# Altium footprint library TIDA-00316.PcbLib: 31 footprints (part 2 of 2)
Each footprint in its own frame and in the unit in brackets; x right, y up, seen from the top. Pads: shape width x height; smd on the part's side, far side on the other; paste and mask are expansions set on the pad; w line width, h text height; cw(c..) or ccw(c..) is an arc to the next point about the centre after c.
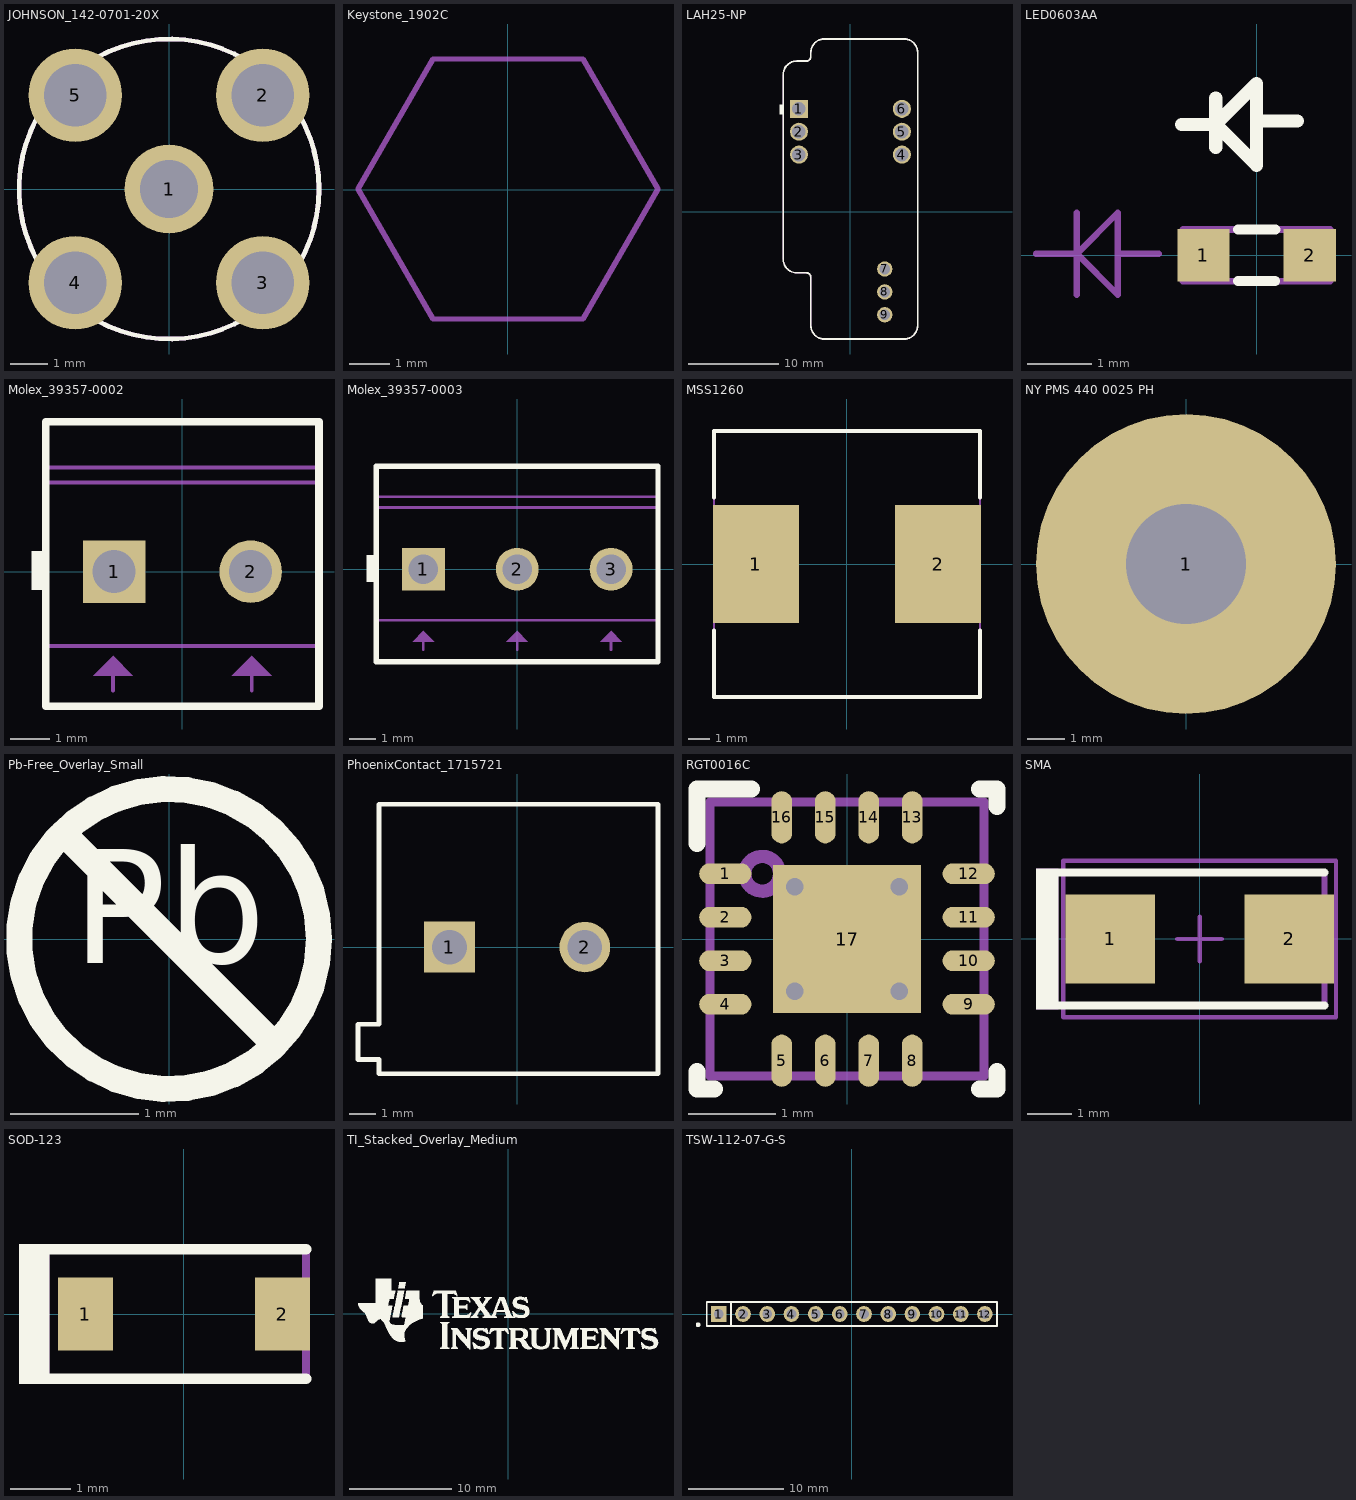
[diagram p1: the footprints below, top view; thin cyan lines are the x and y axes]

## JOHNSON_142-0701-20X [mil] "Johnson Components recommended land pattern"
height 375
pads (5):
  round 95 hole 62: 1(0,0)
  round 100 hole 67: 2(100,100) 3(100,-100) 4(-100,-100) 5(-100,100)
Top Overlay:
  circle w5: c0,0 r160
Mechanical 5:
  circle w5: c0,0 r160
  text ".Designator" at -121,-18 h30
3D body: height 375, standoff -155, extent -155.99,-155.8 156.01,155.8

## Keystone_1902C [mil] "Hex Standoff, 4-40 threaded, nylon"
height 500
pads (1):
  round 1 on Mech3: 0(0,0)
Mechanical 5:
  lines w5: -145.29,0.49 -72.56,-125.49 72.92,-125.49 145.65,0.49 72.92,126.47 -72.56,126.47 -145.29,0.49
  text ".Designator" at -60,-20 h30
3D body: height 501, standoff 1, extent -144.95,-125.98 146,125.98

## LAH25-NP [mm] "TH, 9-Leads, Body 14.93x33.3mm"
height 21.2
pads (9):
  rect 2x2 hole 1.5: 1(-5.715,11.43)
  round 2 hole 1.5: 2(-5.715,8.89) 3(-5.715,6.35) 4(5.715,6.35) 5(5.715,8.89) 6(5.715,11.43)
  round 1.7 hole 1.2: 7(3.81,-6.35) 8(3.81,-8.89) 9(3.81,-11.43)
Top Overlay:
  region: -7.9,11.9 -7.9,10.8 -7.465,10.8 -7.465,11.9
  lines w0.2: -4.402,-7.114 -4.402,-7.122 -4.401,-7.13 -4.401,-7.138 -4.4,-7.146 -4.4,-7.153 -4.4,-7.161 ; -7.465,-5.27 ccw(c-5.965,-5.27) -5.965,-6.77 -4.9,-6.77 cw(c-4.9,-7.27) -4.4,-7.27 -4.4,-12.62 ccw(c-2.9,-12.62) -2.9,-14.12 5.965,-14.12 ccw(c5.965,-12.62) 7.465,-12.62 7.465,17.68 ccw(c5.965,17.68) 5.965,19.18 -2.9,19.18 ccw(c-2.9,17.68) -4.4,17.68 -4.4,17.23 cw(c-4.9,17.23) -4.9,16.73 -5.965,16.73 ccw(c-5.965,15.23) -7.465,15.23 -7.465,-5.27
Mechanical 5:
  lines w0.1: -4.402,-7.114 -4.402,-7.122 -4.401,-7.13 -4.401,-7.138 -4.4,-7.146 -4.4,-7.153 -4.4,-7.161 ; -7.465,-5.27 ccw(c-5.965,-5.27) -5.965,-6.77 -4.9,-6.77 cw(c-4.9,-7.27) -4.4,-7.27 -4.4,-12.62 ccw(c-2.9,-12.62) -2.9,-14.12 5.965,-14.12 ccw(c5.965,-12.62) 7.465,-12.62 7.465,17.68 ccw(c5.965,17.68) 5.965,19.18 -2.9,19.18 ccw(c-2.9,17.68) -4.4,17.68 -4.4,17.23 cw(c-4.9,17.23) -4.9,16.73 -5.965,16.73 ccw(c-5.965,15.23) -7.465,15.23 -7.465,-5.27
  text ".Designator" at 0.432,3.581 h0.76
3D body: height 21.15, standoff -3.55, extent -7.439,-14.12 7.5,19.18

## LED0603AA [mil]
pads (2):
  rect 32x32 smd: 1(-32.48,0) 2(32.48,0)
Top Overlay:
  lines w6: -11.42,-15.75 11.42,-15.75 ; -11.42,15.75 11.42,15.75
  lines w8: -46,80 -25,80 ; -25,66 -25,96 ; 0,82 25,82 ; -25,80 0,55 0,105 -25,80
Mechanical 5:
  lines w4: -45,-15.75 45,-15.75 45,15.75 -45,15.75 -45,-15.75
  text ".Designator" at 31,62 h30
Mechanical 15:
  lines w1: -31.5,-15.75 -31.5,15.75 31.5,15.75 31.5,-15.75 -31.5,-15.75
  lines w3.94: -134.79,0.96 -109.79,0.96 ; -109.79,-24.04 -109.79,25.96 ; -84.79,0.96 -59.79,0.96 ; -109.79,0.96 -84.79,-24.04 -84.79,25.96 -109.79,0.96

## Molex_39357-0002 [mm] "Terminal Block, 3.5 mm, 2x1, TH"
height 8.51
pads (2):
  rect 1.6x1.6 hole 1.1: 1(-1.75,0)
  round 1.6 hole 1.1: 2(1.75,0)
Top Overlay:
  region: -3.864,0.523 -3.864,-0.477 -3.509,-0.477 -3.509,0.523
  lines w0.2: -3.5,-3.45 -3.5,3.84 3.5,3.84 3.5,-3.45 -3.5,-3.45
Mechanical 5:
  region: -2.286,-2.667 -1.27,-2.667 -1.778,-2.159
  region: 1.27,-2.667 2.286,-2.667 1.778,-2.159
  lines w0.1: -3.5,-1.905 3.5,-1.905 ; -3.5,2.286 3.5,2.286 ; -3.5,2.667 3.5,2.667 ; -1.778,-3.048 -1.778,-2.667 ; 1.778,-3.048 1.778,-2.667 ; -3.5,-3.45 3.5,-3.45 3.5,3.84 -3.5,3.84 -3.5,-3.45
  text ".Designator" at 0.787,1.651 h0.76
3D body: height 8.51, standoff -3.5, extent -3.55,-3.45 3.562,3.84

## Molex_39357-0003 [mm] "Terminal Block, 3.5 mm, 3x1, TH"
height 8.51
pads (3):
  rect 1.6x1.6 hole 1.1: 1(-3.5,0)
  round 1.6 hole 1.1: 2(0,0) 3(3.5,0)
Top Overlay:
  region: -5.614,0.523 -5.614,-0.477 -5.259,-0.477 -5.259,0.523
  lines w0.2: -5.25,-3.45 -5.25,3.84 5.25,3.84 5.25,-3.45 -5.25,-3.45
Mechanical 5:
  region: -3.9,-2.7 -3.1,-2.7 -3.5,-2.3
  region: -0.4,-2.7 0.4,-2.7 0,-2.3
  region: 3.1,-2.7 3.9,-2.7 3.5,-2.3
  lines w0.1: -5.25,-1.9 5.25,-1.9 ; -5.25,2.3 5.25,2.3 ; -5.25,2.7 5.25,2.7 ; -3.5,-3 -3.5,-2.7 ; 0,-3 0,-2.7 ; 3.5,-3 3.5,-2.7 ; -5.25,-3.45 5.25,-3.45 5.25,3.84 -5.25,3.84 -5.25,-3.45
  text ".Designator" at 0.838,1.799 h0.76
3D body: height 8.51, standoff -3.5, extent -5.25,-3.45 5.164,3.84

## MSS1260 [mm]
height 6.2
pads (2):
  rect 4x5.5 smd: 1(-4.25,0) 2(4.25,0)
Top Overlay:
  lines w0.178: -6.2,-3.1 -6.2,-6.2 0,-6.2 6.2,-6.2 6.2,-3.1 ; -6.2,3.1 -6.2,6.2 0,6.2 6.2,6.2 6.2,3.1
Mechanical 5:
  lines w0.102: -6.2,-6.175 -6.2,6.175 -6.175,6.2 6.175,6.2 6.2,6.175 6.2,-6.2 -6.175,-6.2 -6.2,-6.175
  text ".Designator" at 0.457,0.406 h0.76
3D body: height 6.25, standoff 0.02, extent -6.15,-6.15 6.15,6.15

## NY PMS 440 0025 PH [mm] "4-40 nylon screw and mounting hole"
height 1.905
pads (1):
  round 8 hole 3.2: 1(0,0)
Mechanical 5:
  circle w0.127: c0,0 r3.789
  text ".Designator" at -1.524,-0.508 h0.76
3D body: height 2.69, standoff -8.74, extent -3.302,-3.3 3.296,3.3

## Pb-Free_Overlay_Small [mm]
Top Overlay:
  circle w0.203: c0,0 r1.168
  lines w0.203: -0.826,0.826 0.826,-0.826
  text "Pb" at -0.752,-0.48 h1.52

## PhoenixContact_1715721 [mm] "Phoenix Contact 1715721 used on LM3445 design from Longmont"
height 13.8
pads (2):
  rect 1.905x1.905 hole 1.3: 1(-2.54,0)
  round 1.9 hole 1.3: 2(2.54,0)
Top Overlay:
  lines w0.178: -5.182,-4.75 -5.182,-4.216 -5.969,-4.216 -5.969,-2.896 -5.182,-2.896 -5.182,5.359 ; -5.156,-4.75 5.283,-4.75 5.283,5.359 -5.156,5.359
Mechanical 5:
  lines w0.127: -5.182,-4.75 -5.182,-4.216 -5.969,-4.216 -5.969,-2.896 -5.182,-2.896 -5.182,5.359 ; -5.156,-4.75 5.283,-4.75 5.283,5.359 -5.156,5.359
  text ".Designator" at 0.406,2.718 h0.76
3D body: height 14.2, standoff -3.5, extent -5.817,-4.598 5.084,5.202

## RGT0016C [mm] "QFN, 16-Leads, Body 3x3mm, Pitch 0.5mm, Thermal Pad 1.7x1.7mm, TI Recommended"
height 1
pads (17):
  oval 0.6x0.24 smd: 1(-1.4,0.75) 2(-1.4,0.25) 3(-1.4,-0.25) 4(-1.4,-0.75) 9(1.4,-0.75) 10(1.4,-0.25) 11(1.4,0.25) 12(1.4,0.75)
  oval 0.24x0.6 smd: 5(-0.75,-1.4) 6(-0.25,-1.4) 7(0.25,-1.4) 8(0.75,-1.4) 13(0.75,1.4) 14(0.25,1.4) 15(-0.25,1.4) 16(-0.75,1.4)
  rect 1.7x1.7 smd paste-0.85 mask+0.064: 17(0,0)
via 0.6,0.6 diameter 0.5 hole 0.2
via 0.6,-0.6 diameter 0.5 hole 0.2
via -0.6,-0.6 diameter 0.5 hole 0.2
via -0.6,0.6 diameter 0.5 hole 0.2
Top Overlay:
  lines w0.2: -1.725,-1.525 -1.725,-1.725 -1.525,-1.725 ; -1.725,1.1 -1.725,1.725 -1.1,1.725 ; 1.525,-1.725 1.725,-1.725 1.725,-1.525 ; 1.525,1.725 1.725,1.725 1.725,1.525
Top Paste:
  rectangle: -0.774,-0.776 0.775,0.773
Mechanical 5:
  circle w0.152: c-0.975,0.75 r0.2
  lines w0.1: -1.575,-1.575 1.575,-1.575 1.575,1.575 -1.575,1.575 -1.575,-1.575
  text ".Designator" at -0.584,-2.032 h0.76
3D body: height 1, standoff 0, extent -1.575,-1.575 1.575,1.575
3D body: height 1.01, standoff 0.5, extent -1.178,0.547 -0.772,0.953

## SMA [mm] "Molded Diode, 2-Leads, Body 4.3x2.6mm, IPC Medium Density, based on OnSemi component dimensions and land pattern"
height 2.27
pads (2):
  rect 2x2 smd: 1(-2,0) 2(2,0)
Top Overlay:
  rectangle: -3.658,-1.575 -3.15,1.575
  lines w0.178: -3.327,-1.486 2.794,-1.486 ; -3.327,1.486 2.794,1.486
Mechanical 5:
  rectangle: -3.658,-1.575 -3.15,1.575
  lines w0.127: -3.327,-1.486 2.794,-1.486 2.794,1.486 -3.327,1.486
  text ".Designator" at 0.487,0.432 h0.76
Mechanical 15:
  lines w0.1: -0.5,0 0.5,0 ; 0,-0.5 0,0.5 ; -3.05,-1.75 -3.05,1.75 3.05,1.75 3.05,-1.75 -3.05,-1.75
3D body: height 2.42, standoff 0.02, extent -2.6,-1.3 2.6,1.3

## SOD-123 [mm] "On Semi recommended land pattern"
height 1.35
pads (2):
  rect 0.915x1.22 smd: 1(-1.637,0) 2(1.637,0)
Top Overlay:
  rectangle: -2.743,-1.168 -2.235,1.168
  lines w0.178: -2.413,-1.079 2.032,-1.079 ; -2.413,1.079 2.032,1.079
Mechanical 5:
  rectangle: -2.743,-1.168 -2.235,1.168
  lines w0.127: -2.413,-1.079 2.032,-1.079 2.032,1.079 -2.413,1.079
  text ".Designator" at 0.483,0.483 h0.76
3D body: height 1.35, standoff 0, extent -1.932,-0.9 1.932,0.9

## TI_Stacked_Overlay_Medium [mm]
Top Overlay:
  drawing of 18 lines, arcs and shapes, not listed

## TSW-112-07-G-S [mm] "Samtec 100mil, 1x12, 230 mil above insulator"
height 8.382
pads (12):
  rect 1.65x1.65 hole 1.016 mask+0: 1(-13.97,0)
  round 1.65 hole 1.016 mask+0: 2(-11.43,0) 3(-8.89,0) 4(-6.35,0) 5(-3.81,0) 6(-1.27,0) 7(1.27,0) 8(3.81,0) 9(6.35,0) 10(8.89,0) 11(11.43,0) 12(13.97,0)
Top Overlay:
  circle w0.25: c-16.14,-1.13 r0.125
  lines w0.178: -12.7,-1.27 -12.7,1.27 ; -15.24,-1.27 -15.24,1.27 15.24,1.27 15.24,-1.27 -15.24,-1.27
Mechanical 5:
  rectangle: -14.478,-0.508 -13.462,0.508
  lines w0.127: -15.24,-1.27 15.24,-1.27 15.24,1.27 -15.24,1.27 -15.24,-1.27
  text ".Designator" at -15.596,-0.635 h0.76
3D body: height 8.38, standoff -2.54, extent -15.24,-1.27 15.24,1.27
